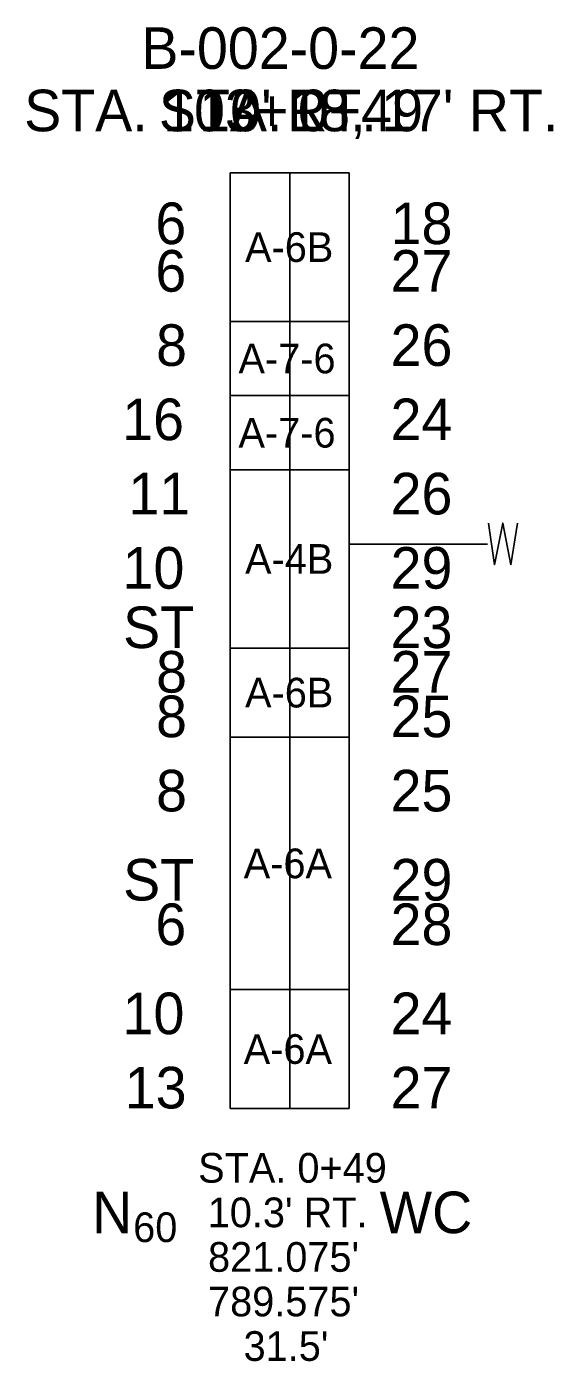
# Model space of a CAD drawing. Extents: x -0.89 to 0.89, y -4 to 0.49.
import ezdxf

# ---------------------------------------------------------------- set-up
doc = ezdxf.new("R2010")
doc.units = 0
for name, color, linetype in [('GT_Project_Cells', 7, 'Continuous'), ('GT_Project_Soil_Boring', 7, 'Continuous'), ('GT_Project_Text', 7, 'Continuous'), ('SC_Scratch1', 7, 'Continuous'), ('SC_Scratch2', 7, 'Continuous')]:
    doc.layers.add(name, color=color, linetype=linetype)

msp = doc.modelspace()

# ---------------------------------------------------------------- linework, layer by layer
at = {"layer": 'GT_Project_Cells'}
msp.add_line((0.6667, -1.25), (0.2, -1.25), dxfattribs=at)
msp.add_lwpolyline([(0.6695, -1.1793), (0.6904, -1.3193), (0.718, -1.1793), (0.7455, -1.3193), (0.7676, -1.1793)], dxfattribs=at)
at = {"layer": 'GT_Project_Soil_Boring'}
for p, q in [((-0.2, 0), (0.2, 0)), ((-0.2, 0), (-0.2, -3.15)), ((0, 0), (0, -3.15)), ((0.2, 0), (0.2, -3.15)), ((-0.2, -0.5), (0.2, -0.5)), ((-0.2, -0.75), (0.2, -0.75)), ((-0.2, -1), (0.2, -1)), ((-0.2, -1.6), (0.2, -1.6)), ((-0.2, -1.9), (0.2, -1.9)), ((-0.2, -2.75), (0.2, -2.75)), ((-0.2, -3.15), (0.2, -3.15))]:
    msp.add_line(p, q, dxfattribs=at)
at = {"layer": 'GT_Project_Text'}
msp.add_line((-0.5272, -3.5), (-0.5272, -3.5), dxfattribs=at)

# ---------------------------------------------------------------- texts
for s, height, p in [('B-002-0-22', 0.14, (-0.4996, 0.35)), ("STA. 103+18, 17' RT.", 0.14, (-0.8944, 0.14)), ('6', 0.14, (-0.4524, -0.24)), ('18', 0.14, (0.34, -0.24)), ('6', 0.14, (-0.4524, -0.4)), ('27', 0.14, (0.34, -0.4)), ('8', 0.14, (-0.45, -0.65)), ('26', 0.14, (0.34, -0.65)), ('16', 0.14, (-0.5641, -0.9)), ('24', 0.14, (0.34, -0.9)), ('11', 0.14, (-0.5434, -1.15)), ('26', 0.14, (0.34, -1.15)), ('10', 0.14, (-0.5629, -1.4)), ('29', 0.14, (0.34, -1.4)), ('ST', 0.14, (-0.5611, -1.6)), ('23', 0.14, (0.34, -1.6)), ('8', 0.14, (-0.45, -1.75)), ('27', 0.14, (0.34, -1.75)), ('8', 0.14, (-0.45, -1.9)), ('25', 0.14, (0.34, -1.9)), ('8', 0.14, (-0.45, -2.15)), ('25', 0.14, (0.34, -2.15)), ('ST', 0.14, (-0.5611, -2.45)), ('29', 0.14, (0.34, -2.45)), ('6', 0.14, (-0.4524, -2.6)), ('28', 0.14, (0.34, -2.6)), ('10', 0.14, (-0.5629, -2.9)), ('24', 0.14, (0.34, -2.9)), ('13', 0.14, (-0.5555, -3.15)), ('27', 0.14, (0.34, -3.15)), ('N', 0.14, (-0.6652, -3.57)), ('WC', 0.14, (0.303, -3.57)), ('60', 0.1, (-0.5272, -3.6))]:
    msp.add_text(s, height=height, dxfattribs=at).set_placement(p)
at = {"layer": 'SC_Scratch1'}
for s, height, p in [('STA. 0+49', 0.14, (-0.4406, 0.14)), ("10' RT.", 0.14, (-0.3046, 0.14)), ('A-6B', 0.1, (-0.1503, -0.3)), ('A-7-6', 0.1, (-0.1725, -0.675)), ('A-7-6', 0.1, (-0.1725, -0.925)), ('A-4B', 0.1, (-0.1503, -1.35)), ('A-6B', 0.1, (-0.1503, -1.8)), ('A-6A', 0.1, (-0.1548, -2.375)), ('A-6A', 0.1, (-0.1548, -3))]:
    msp.add_text(s, height=height, dxfattribs=at).set_placement(p)
at = {"layer": 'SC_Scratch2'}
for s, p in [('STA. 0+49', (-0.3083, -3.4)), ("10.3' RT.", (-0.2761, -3.55)), ("821.075'", (-0.275, -3.7)), ("789.575'", (-0.275, -3.85)), ("31.5'", (-0.1553, -4))]:
    msp.add_text(s, height=0.1, dxfattribs=at).set_placement(p)

doc.saveas('drawing.dxf')
